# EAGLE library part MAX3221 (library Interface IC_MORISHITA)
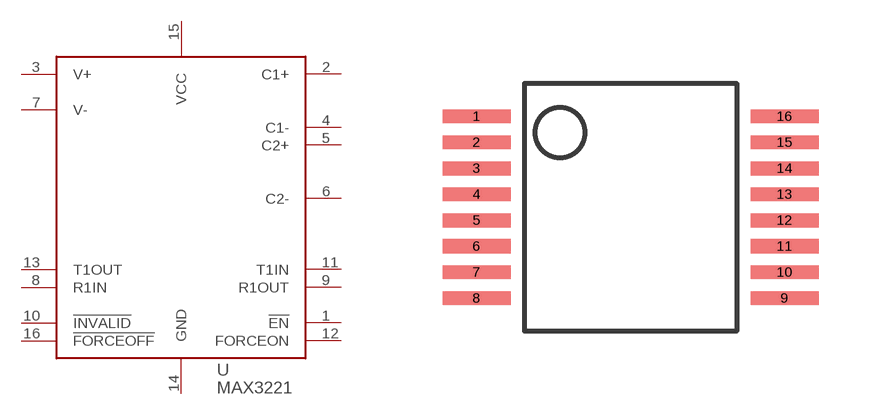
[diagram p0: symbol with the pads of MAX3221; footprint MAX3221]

Designator prefix U

## MAX3221  [MAX3221]
1  !EN
2  C1+
3  V+
4  C1-
5  C2+
6  C2-
7  V-
8  R1IN
9  R1OUT
10  !INVALID
11  T1IN
12  FORCEON
13  T1OUT
14  GND
15  VCC
16  !FORCEOFF

## Footprint MAX3221 (pad centres in mm)
16pin SSOP Package
smd 1.7 x 0.35: 1 -3.85,2.275; 2 -3.85,1.625; 3 -3.85,0.975; 4 -3.85,0.325; 5 -3.85,-0.325; 6 -3.85,-0.975; 7 -3.85,-1.625; 8 -3.85,-2.275; 9 3.85,-2.275; 10 3.85,-1.625; 11 3.85,-0.975; 12 3.85,-0.325; 13 3.85,0.325; 14 3.85,0.975; 15 3.85,1.625; 16 3.85,2.275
